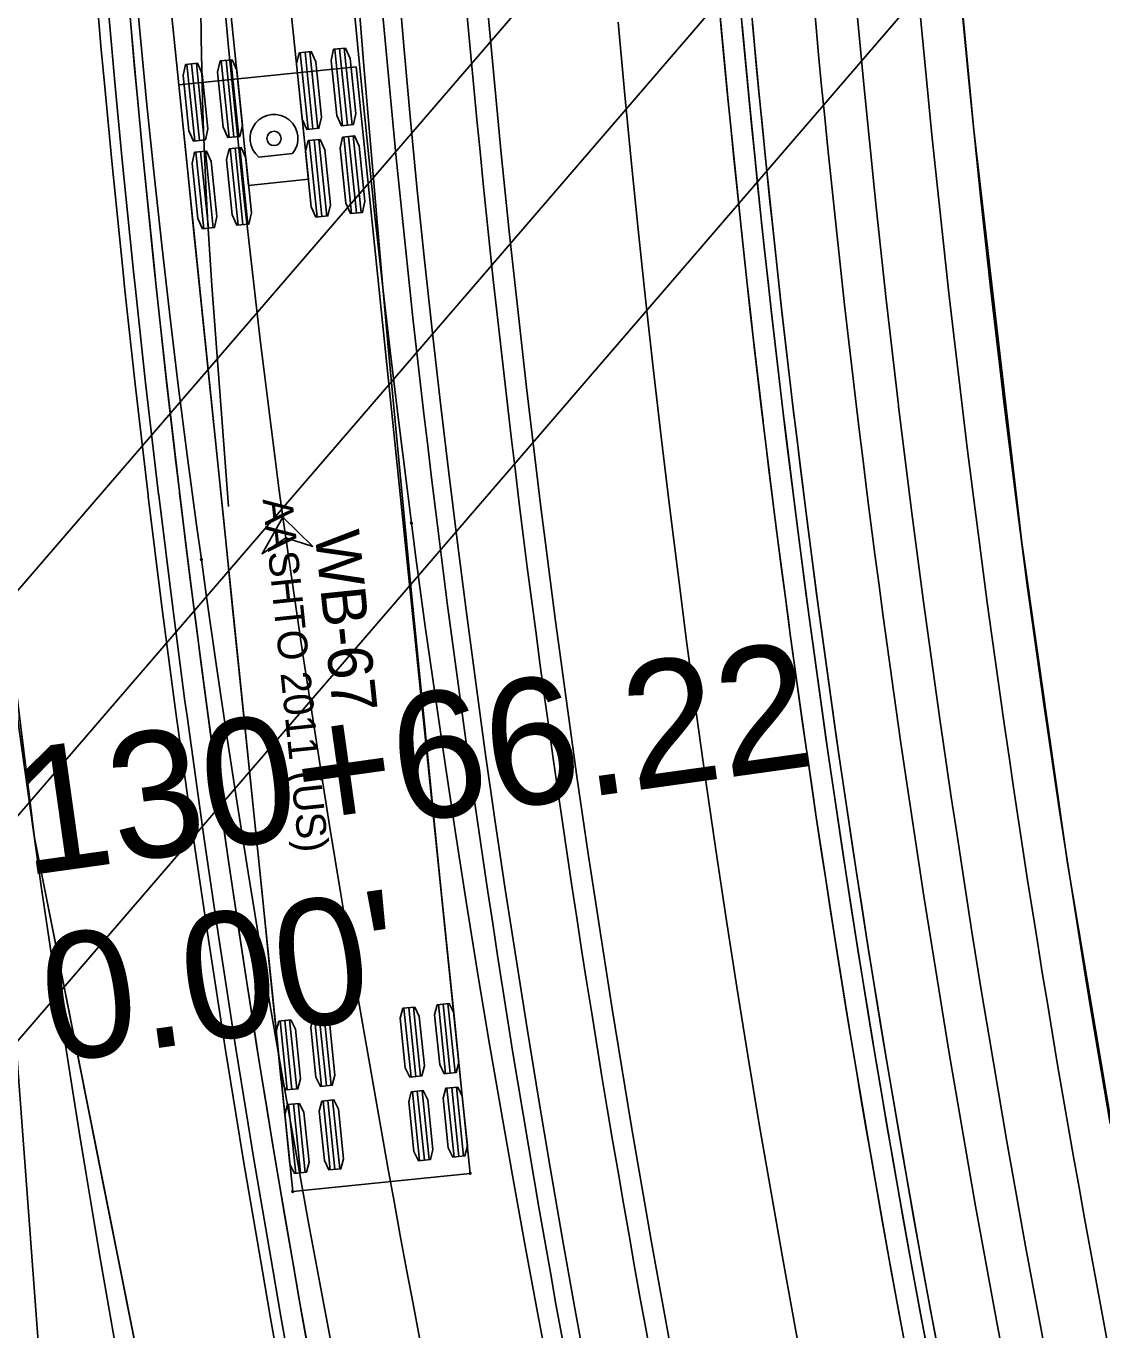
# Model space of a CAD drawing. Extents: x -70 to 701944, y -4 to 666871.
# Drawn here: x 668209.6 to 668260.8, y 656266.5 to 656328.6 of the extents above; entities that cross this region are included whole.
import ezdxf

# ---------------------------------------------------------------- set-up
doc = ezdxf.new("R2010")
doc.units = 0
for name, color, linetype in [('R_Draft', 7, 'Continuous'), ('R_Horz Alg', 7, 'Continuous'), ('R_No Plot', 7, 'Continuous'), ('R_Proposed Road', 7, 'Continuous'), ('R_Striping', 7, 'Continuous'), ('R_Water', 7, 'Continuous'), ('T_Indications', 7, 'Continuous'), ('T_Vehicle Path Lt Major', 7, 'Continuous'), ('T_Vehicle Path Lt Minor', 7, 'Continuous'), ('T_Vehicle Path Rt', 7, 'Continuous')]:
    doc.layers.add(name, color=color, linetype=linetype)

msp = doc.modelspace()

# ---------------------------------------------------------------- linework, layer by layer
at = {"layer": 'R_Draft'}
msp.add_line((668219.207, 656305.742), (668218.421, 656316.262), dxfattribs=at)
msp.add_arc((668407.894, 656330.41), 190, 128.29142, 184.27052, dxfattribs=at)
at = {"layer": 'R_Horz Alg'}
msp.add_line((668214.129, 656212.597), (668204.795, 656337.586), dxfattribs=at)
msp.add_arc((668919.004, 656390.918), 716.197, 184.270523, 204.123313, dxfattribs=at)
at = {"layer": 'R_No Plot'}
msp.add_line((668146.592, 656218.335), (668259.536, 656349.509), dxfattribs=at)
for points in [[(668203.487, 656355.108), (668251.852, 656358.719), (668253.161, 656341.197), (668253.893, 656332.226), (668254.707, 656323.663), (668256.989, 656304.018), (668259.175, 656288.746), (668262.093, 656271.387), (668265.097, 656255.918), (668267.006, 656246.759), (668268.493, 656237.565), (668221.915, 656226.584), (668216.775, 656255.73), (668213.367, 656272.838), (668209.96, 656289.947), (668208.341, 656303.042), (668205.828, 656325.201), (668204.769, 656337.932)], [(668145.584, 656319.648), (668148.917, 656289.832), (668153.337, 656260.517), (668160.437, 656224.08), (668163.658, 656212.851), (668221.915, 656226.584), (668216.775, 656255.73), (668209.96, 656289.947), (668206.722, 656316.137), (668205.828, 656325.201), (668149.946, 656320.05)]]:
    msp.add_lwpolyline(points, close=True, dxfattribs=at)
at = {"layer": 'R_Proposed Road'}
for points in [[(668221.755, 656264.047), (668221.213, 656267.064), (668220.82, 656269.302), (668219.923, 656274.565), (668219.552, 656276.819), (668219.067, 656279.834), (668218.25, 656285.109), (668218.027, 656286.596), (668217.602, 656289.491), (668217.473, 656290.391), (668216.735, 656295.678), (668216.639, 656296.393), (668216.038, 656300.97), (668215.388, 656306.209), (668215.38, 656306.268), (668214.763, 656311.57), (668214.273, 656316.041), (668214.185, 656316.877), (668213.647, 656322.189), (668213.297, 656325.888), (668213.15, 656327.504), (668212.9, 656330.35)], [(668222.247, 656264.136), (668221.706, 656267.151), (668221.312, 656269.388), (668220.417, 656274.647), (668220.045, 656276.899), (668219.561, 656279.912), (668218.744, 656285.184), (668218.522, 656286.669), (668218.097, 656289.562), (668217.968, 656290.462), (668217.231, 656295.745), (668217.134, 656296.46), (668216.534, 656301.034), (668215.884, 656306.268), (668215.877, 656306.328), (668215.26, 656311.626), (668214.771, 656316.094), (668214.682, 656316.93), (668214.145, 656322.237), (668213.795, 656325.934), (668213.648, 656327.548), (668213.398, 656330.393)], [(668223.231, 656264.315), (668222.69, 656267.326), (668222.297, 656269.56), (668221.403, 656274.811), (668221.032, 656277.06), (668220.548, 656280.069), (668219.733, 656285.333), (668219.511, 656286.816), (668219.087, 656289.705), (668218.958, 656290.604), (668218.222, 656295.879), (668218.125, 656296.593), (668217.526, 656301.161), (668216.877, 656306.388), (668216.87, 656306.447), (668216.253, 656311.738), (668215.765, 656316.199), (668215.677, 656317.034), (668215.14, 656322.334), (668214.79, 656326.025), (668214.644, 656327.638), (668214.394, 656330.479)], [(668251.714, 656264.298), (668250.779, 656269.328), (668250.259, 656272.219), (668249.882, 656274.365), (668249.023, 656279.408), (668248.667, 656281.568), (668248.202, 656284.458), (668247.419, 656289.514), (668247.206, 656290.938), (668246.799, 656293.713), (668246.674, 656294.575), (668245.968, 656299.642), (668245.875, 656300.328), (668245.299, 656304.715), (668244.676, 656309.735), (668244.669, 656309.792), (668244.077, 656314.873), (668243.608, 656319.158), (668243.524, 656319.959), (668243.008, 656325.049), (668242.672, 656328.595), (668242.531, 656330.143)], [(668261.211, 656276.338), (668260.367, 656281.296), (668260.017, 656283.42), (668259.56, 656286.26), (668258.79, 656291.231), (668258.58, 656292.631), (668258.18, 656295.358), (668258.058, 656296.207), (668257.364, 656301.188), (668257.272, 656301.861), (668256.706, 656306.174), (668256.094, 656311.109), (668256.087, 656311.165), (668255.505, 656316.161), (668255.044, 656320.373), (668254.961, 656321.161), (668254.454, 656326.165), (668254.124, 656329.65)], [(668258.1, 656265.51), (668257.174, 656270.492), (668256.659, 656273.355), (668256.286, 656275.48), (668255.435, 656280.475), (668255.082, 656282.615), (668254.622, 656285.477), (668253.846, 656290.484), (668253.635, 656291.895), (668253.232, 656294.643), (668253.109, 656295.497), (668252.409, 656300.516), (668252.317, 656301.195), (668251.747, 656305.54), (668251.129, 656310.512), (668251.123, 656310.568), (668250.536, 656315.601), (668250.072, 656319.845), (668249.988, 656320.638), (668249.478, 656325.68), (668249.145, 656329.191)], [(668252.696, 656264.484), (668251.763, 656269.507), (668251.244, 656272.394), (668250.867, 656274.536), (668250.009, 656279.572), (668249.654, 656281.729), (668249.19, 656284.615), (668248.408, 656289.663), (668248.195, 656291.085), (668247.788, 656293.856), (668247.664, 656294.717), (668246.959, 656299.777), (668246.866, 656300.461), (668246.291, 656304.841), (668245.669, 656309.854), (668245.662, 656309.911), (668245.071, 656314.985), (668244.603, 656319.263), (668244.518, 656320.064), (668244.004, 656325.146), (668243.668, 656328.687)], [(668253.187, 656264.578), (668252.255, 656269.596), (668251.736, 656272.482), (668251.36, 656274.622), (668250.503, 656279.654), (668250.148, 656281.81), (668249.684, 656284.693), (668248.902, 656289.738), (668248.689, 656291.159), (668248.283, 656293.927), (668248.159, 656294.788), (668247.454, 656299.844), (668247.362, 656300.528), (668246.787, 656304.905), (668246.165, 656309.914), (668246.158, 656309.971), (668245.568, 656315.041), (668245.1, 656319.316), (668245.015, 656320.116), (668244.501, 656325.195), (668244.166, 656328.732)]]:
    msp.add_lwpolyline(points, dxfattribs=at)
for radius in [707.197, 725.197]:
    msp.add_arc((668919.004, 656390.918), radius, 184.270523, 204.123313, dxfattribs=at)
at = {"layer": 'R_Striping'}
for radius, start, end in [(691.197, 184.270523, 192.404344), (695.197, 184.270523, 200.430569), (737.197, 184.194321, 200.430569)]:
    msp.add_arc((668919.004, 656390.918), radius, start, end, dxfattribs=at)
at = {"layer": 'R_Water'}
for p, q in [((668254.821, 656354.76), (668141.288, 656222.903)), ((668265.43, 656345.625), (668151.897, 656213.768))]:
    msp.add_line(p, q, dxfattribs=at)
at = {"layer": 'T_Indications'}
for radius in [674.697, 669.697, 679.197, 678.197, 677.697]:
    msp.add_arc((668919.004, 656390.918), radius, 184.270523, 192.404344, dxfattribs=at)
at = {"layer": 'T_Vehicle Path Lt Major'}
for p, q in [((668219.079, 656331.577), (668220.164, 656321.033)), ((668223.016, 656321.327), (668221.93, 656331.871)), ((668219.318, 656327.011), (668219.694, 656323.364)), ((668222.626, 656327.352), (668223.001, 656323.704)), ((668222.854, 656327.375), (668223.229, 656323.728)), ((668223.082, 656327.399), (668223.457, 656323.751)), ((668224.267, 656327.521), (668224.643, 656323.873)), ((668224.495, 656327.544), (668224.871, 656323.897)), ((668224.723, 656327.568), (668225.099, 656323.92)), ((668225.295, 656326.688), (668216.84, 656325.818)), ((668217.221, 656326.795), (668217.597, 656323.148)), ((668217.449, 656326.819), (668217.825, 656323.171)), ((668217.677, 656326.842), (668218.053, 656323.195)), ((668218.862, 656326.964), (668219.238, 656323.317)), ((668219.09, 656326.988), (668219.466, 656323.34)), ((668230.723, 656273.967), (668225.295, 656326.688)), ((668216.84, 656325.818), (668222.268, 656273.097)), ((668216.84, 656325.818), (668216.84, 656325.818)), ((668224.697, 656323.343), (668225.073, 656319.695)), ((668224.925, 656323.366), (668225.301, 656319.719)), ((668225.153, 656323.39), (668225.529, 656319.742)), ((668218.107, 656322.664), (668218.483, 656319.017)), ((668219.293, 656322.786), (668219.668, 656319.139)), ((668219.521, 656322.81), (668219.896, 656319.163)), ((668219.749, 656322.833), (668220.124, 656319.186)), ((668223.056, 656323.174), (668223.432, 656319.526)), ((668223.284, 656323.197), (668223.659, 656319.55)), ((668223.512, 656323.221), (668223.887, 656319.573)), ((668217.651, 656322.617), (668218.027, 656318.97)), ((668217.879, 656322.641), (668218.255, 656318.994)), ((668220.654, 656322.382), (668222.262, 656322.548)), ((668220.164, 656321.033), (668223.016, 656321.327)), ((668227.563, 656281.835), (668227.901, 656278.552)), ((668227.791, 656281.858), (668228.129, 656278.576)), ((668228.019, 656281.882), (668228.357, 656278.599)), ((668229.205, 656282.004), (668229.543, 656278.721)), ((668229.433, 656282.027), (668229.77, 656278.745)), ((668229.66, 656282.051), (668229.998, 656278.768)), ((668221.661, 656281.227), (668221.999, 656277.944)), ((668221.889, 656281.251), (668222.227, 656277.968)), ((668222.117, 656281.274), (668222.455, 656277.991)), ((668223.302, 656281.396), (668223.64, 656278.113)), ((668223.53, 656281.42), (668223.868, 656278.137)), ((668223.758, 656281.443), (668224.096, 656278.16)), ((668229.614, 656278.025), (668229.952, 656274.742)), ((668229.842, 656278.048), (668230.18, 656274.766)), ((668230.07, 656278.072), (668230.408, 656274.789)), ((668223.712, 656277.417), (668224.05, 656274.134)), ((668223.94, 656277.441), (668224.278, 656274.158)), ((668224.168, 656277.464), (668224.506, 656274.181)), ((668227.973, 656277.856), (668228.311, 656274.573)), ((668228.201, 656277.879), (668228.539, 656274.597)), ((668228.429, 656277.903), (668228.767, 656274.62)), ((668222.071, 656277.248), (668222.409, 656273.966)), ((668222.299, 656277.272), (668222.637, 656273.989)), ((668222.527, 656277.295), (668222.865, 656274.012)), ((668222.268, 656273.097), (668230.723, 656273.967))]:
    msp.add_line(p, q, dxfattribs=at)
for points in [[(668230.723, 656273.967), (668230.361, 656277.482), (668229.999, 656280.997), (668229.639, 656284.511), (668229.279, 656288.026), (668228.923, 656291.542), (668228.57, 656295.057), (668228.221, 656298.573), (668227.878, 656302.09), (668227.54, 656305.607), (668227.208, 656309.125), (668226.883, 656312.643), (668226.565, 656316.162), (668226.255, 656319.682), (668225.953, 656323.202), (668225.66, 656326.724), (668225.66, 656326.724), (668225.386, 656330.129)], [(668222.268, 656273.097), (668221.905, 656276.611), (668221.543, 656280.126), (668221.182, 656283.641), (668220.82, 656287.156), (668220.459, 656290.67), (668220.097, 656294.185), (668219.735, 656297.7), (668219.373, 656301.215), (668219.011, 656304.729), (668218.649, 656308.244), (668218.287, 656311.759), (668217.926, 656315.274), (668217.564, 656318.788), (668217.202, 656322.303), (668216.84, 656325.818), (668216.499, 656329.217)]]:
    msp.add_lwpolyline(points, dxfattribs=at)
for points in [[(668218.806, 656326.959), (668219.375, 656327.017), (668219.599, 656326.524), (668219.869, 656323.898), (668219.75, 656323.37), (668219.181, 656323.311), (668218.957, 656323.804), (668218.687, 656326.43)], [(668222.569, 656327.346), (668223.138, 656327.405), (668223.362, 656326.912), (668223.633, 656324.285), (668223.514, 656323.757), (668222.945, 656323.699), (668222.721, 656324.192), (668222.451, 656326.818)], [(668224.211, 656327.515), (668224.78, 656327.574), (668225.004, 656327.081), (668225.274, 656324.454), (668225.155, 656323.926), (668224.586, 656323.868), (668224.362, 656324.361), (668224.092, 656326.987)], [(668217.165, 656326.79), (668217.734, 656326.848), (668217.958, 656326.355), (668218.228, 656323.729), (668218.109, 656323.201), (668217.54, 656323.142), (668217.316, 656323.635), (668217.046, 656326.261)], [(668224.641, 656323.337), (668225.21, 656323.396), (668225.434, 656322.903), (668225.704, 656320.276), (668225.585, 656319.748), (668225.016, 656319.69), (668224.792, 656320.183), (668224.522, 656322.809)], [(668217.595, 656322.612), (668218.164, 656322.67), (668218.388, 656322.177), (668218.658, 656319.551), (668218.539, 656319.023), (668217.97, 656318.964), (668217.746, 656319.457), (668217.476, 656322.083)], [(668219.236, 656322.781), (668219.805, 656322.839), (668220.029, 656322.346), (668220.299, 656319.72), (668220.181, 656319.192), (668219.612, 656319.133), (668219.388, 656319.626), (668219.117, 656322.252)], [(668222.999, 656323.168), (668223.568, 656323.227), (668223.792, 656322.734), (668224.063, 656320.108), (668223.944, 656319.579), (668223.375, 656319.521), (668223.151, 656320.014), (668222.881, 656322.64)], [(668227.507, 656281.829), (668228.076, 656281.888), (668228.294, 656281.446), (668228.538, 656279.082), (668228.414, 656278.605), (668227.845, 656278.546), (668227.626, 656278.988), (668227.383, 656281.352)], [(668229.148, 656281.998), (668229.717, 656282.057), (668229.936, 656281.615), (668230.179, 656279.251), (668230.055, 656278.774), (668229.486, 656278.715), (668229.267, 656279.157), (668229.024, 656281.521)], [(668221.605, 656281.221), (668222.174, 656281.28), (668222.392, 656280.838), (668222.636, 656278.474), (668222.512, 656277.997), (668221.943, 656277.939), (668221.724, 656278.381), (668221.48, 656280.744)], [(668223.246, 656281.39), (668223.815, 656281.449), (668224.034, 656281.007), (668224.277, 656278.643), (668224.153, 656278.166), (668223.584, 656278.108), (668223.365, 656278.55), (668223.122, 656280.913)], [(668229.558, 656278.019), (668230.127, 656278.078), (668230.345, 656277.636), (668230.589, 656275.272), (668230.465, 656274.795), (668229.896, 656274.736), (668229.677, 656275.178), (668229.434, 656277.542)], [(668223.656, 656277.411), (668224.225, 656277.47), (668224.443, 656277.028), (668224.687, 656274.664), (668224.562, 656274.187), (668223.993, 656274.129), (668223.775, 656274.571), (668223.531, 656276.934)], [(668227.916, 656277.85), (668228.485, 656277.909), (668228.704, 656277.467), (668228.947, 656275.103), (668228.823, 656274.626), (668228.254, 656274.567), (668228.036, 656275.009), (668227.792, 656277.373)], [(668222.014, 656277.242), (668222.583, 656277.301), (668222.802, 656276.859), (668223.045, 656274.495), (668222.921, 656274.018), (668222.352, 656273.96), (668222.133, 656274.402), (668221.89, 656276.765)]]:
    msp.add_lwpolyline(points, close=True, dxfattribs=at)
for centre, radius in [((668221.375, 656323.269), 0.34), ((668230.723, 656273.967), 0.0417), ((668222.268, 656273.097), 0.0417)]:
    msp.add_circle(centre, radius, dxfattribs=at)
msp.add_arc((668221.375, 656323.269), 1.143, 320.87792, 230.87792, dxfattribs=at)
at = {"layer": 'T_Vehicle Path Lt Minor'}
for points in [[(668227.922, 656304.946), (668227.71, 656306.588), (668227.298, 656309.872), (668226.903, 656313.155), (668226.525, 656316.439), (668226.165, 656319.725), (668225.821, 656323.013), (668225.494, 656326.302), (668225.185, 656329.593), (668224.893, 656332.885), (668224.618, 656336.178), (668224.362, 656339.473), (668224.124, 656342.769), (668223.905, 656346.066), (668223.706, 656349.365), (668223.526, 656352.664), (668223.366, 656355.964), (668223.226, 656359.265), (668223.118, 656362.237)], [(668217.916, 656303.206), (668217.69, 656304.867), (668217.235, 656308.187), (668216.814, 656311.519), (668216.414, 656314.854), (668216.033, 656318.192), (668215.669, 656321.532), (668215.324, 656324.874), (668214.997, 656328.217), (668214.688, 656331.562), (668214.398, 656334.909), (668214.125, 656338.258), (668213.871, 656341.608), (668213.635, 656344.959), (668213.417, 656348.311), (668213.218, 656351.665), (668213.036, 656355.019), (668212.872, 656358.375), (668212.741, 656361.396)], [(668236.557, 656254.024), (668236.49, 656254.348), (668235.827, 656257.593), (668235.179, 656260.84), (668234.544, 656264.091), (668233.925, 656267.344), (668233.32, 656270.6), (668232.731, 656273.859), (668232.157, 656277.121), (668231.599, 656280.385), (668231.056, 656283.652), (668230.529, 656286.922), (668230.018, 656290.194), (668229.524, 656293.469), (668229.045, 656296.746), (668228.583, 656300.024), (668228.138, 656303.305), (668227.922, 656304.946)], [(668226.902, 656251.722), (668226.834, 656252.05), (668226.162, 656255.333), (668225.503, 656258.618), (668224.857, 656261.905), (668224.223, 656265.196), (668223.602, 656268.488), (668222.994, 656271.783), (668222.399, 656275.08), (668221.817, 656278.38), (668221.247, 656281.682), (668220.691, 656284.986), (668220.147, 656288.292), (668219.619, 656291.601), (668219.11, 656294.913), (668218.619, 656298.228), (668218.145, 656301.546), (668217.916, 656303.206)]]:
    msp.add_lwpolyline(points, dxfattribs=at)
msp.add_lwpolyline([(668221.792, 656305.23), (668220.811, 656303.487), (668221.933, 656304.24), (668223.222, 656303.831)], close=True, dxfattribs=at)
for centre in [(668221.792, 656305.23), (668221.792, 656305.23), (668227.922, 656304.946), (668227.922, 656304.946), (668217.916, 656303.206), (668217.916, 656303.206)]:
    msp.add_circle(centre, 0.0417, dxfattribs=at)
for centre, radius, start, end in [((668829.967, 656386.67), 613.604, 179.276199, 187.627077), ((669069.119, 656426.3), 855.933, 188.13167, 195.206937)]:
    msp.add_arc(centre, radius, start, end, dxfattribs=at)
at = {"layer": 'T_Vehicle Path Rt'}
for points in [[(668236.289, 656264.323), (668235.684, 656267.626), (668235.096, 656270.931), (668234.523, 656274.239), (668233.967, 656277.55), (668233.426, 656280.864), (668232.902, 656284.18), (668232.393, 656287.499), (668231.901, 656290.82), (668231.425, 656294.143), (668230.965, 656297.469), (668230.521, 656300.797), (668230.093, 656304.127), (668229.681, 656307.459), (668229.285, 656310.793), (668228.906, 656314.129), (668228.542, 656317.466), (668228.195, 656320.806), (668227.873, 656324.148), (668227.575, 656327.494), (668227.288, 656330.84)], [(668246.823, 656263.284), (668246.216, 656266.536), (668245.625, 656269.792), (668245.049, 656273.05), (668244.489, 656276.31), (668243.945, 656279.574), (668243.418, 656282.84), (668242.908, 656286.109), (668242.416, 656289.38), (668241.941, 656292.655), (668241.483, 656295.931), (668241.043, 656299.21), (668240.619, 656302.491), (668240.211, 656305.774), (668239.819, 656309.059), (668239.441, 656312.346), (668239.078, 656315.634), (668238.728, 656318.924), (668238.392, 656322.215), (668238.072, 656325.507), (668237.769, 656328.802)]]:
    msp.add_lwpolyline(points, dxfattribs=at)
for radius, start in [(690.197, 184.287093), (742.197, 184.270523)]:
    msp.add_arc((668919.004, 656390.918), radius, start, 204.123313, dxfattribs=at)

# ---------------------------------------------------------------- texts
at = {"layer": 'R_No Plot'}
for s, height, rotation, p in [('130+66.22 ', 6, 7.96699, (668209.512, 656288.137)), ('+', 0.1, 97.98487, (668209.806, 656291.394)), ("0.00' ", 6, 7.96699, (668210.759, 656279.224))]:
    msp.add_text(s, height=height, rotation=rotation, dxfattribs=at).set_placement(p)
at = {"layer": 'T_Vehicle Path Lt Major'}
for s, height, p in [('AASHTO 2011 (US)', 1.41667, (668220.831, 656306.073)), ('WB-67', 2.125, (668223.309, 656304.486))]:
    msp.add_text(s, height=height, rotation=275.87792, dxfattribs=at).set_placement(p)

doc.saveas('drawing.dxf')
